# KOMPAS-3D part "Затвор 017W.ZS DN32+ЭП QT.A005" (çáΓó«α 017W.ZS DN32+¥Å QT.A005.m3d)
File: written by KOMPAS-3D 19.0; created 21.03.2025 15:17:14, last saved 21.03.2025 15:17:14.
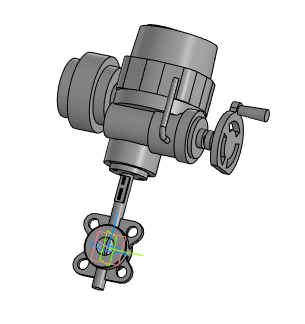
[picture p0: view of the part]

Document properties: Полное имя файла: Затвор 017W.ZS DN32+ЭП QT.A005.a3d

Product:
- Part/product: Затвор 017W.ZS DN32+ЭП QT.A005
    Масса: 37.573

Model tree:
1. Операция без истории:1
